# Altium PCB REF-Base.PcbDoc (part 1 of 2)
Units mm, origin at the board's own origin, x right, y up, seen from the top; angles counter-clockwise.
Board outline 48.01 x 58 mm, 4 copper layers (Top1, VCC, GND, Bottom2), stack 1.833 mm thick; 98 components, 129 nets, 444 pads, 192 vias.
Unrouted connection lines stored in the file: 57.
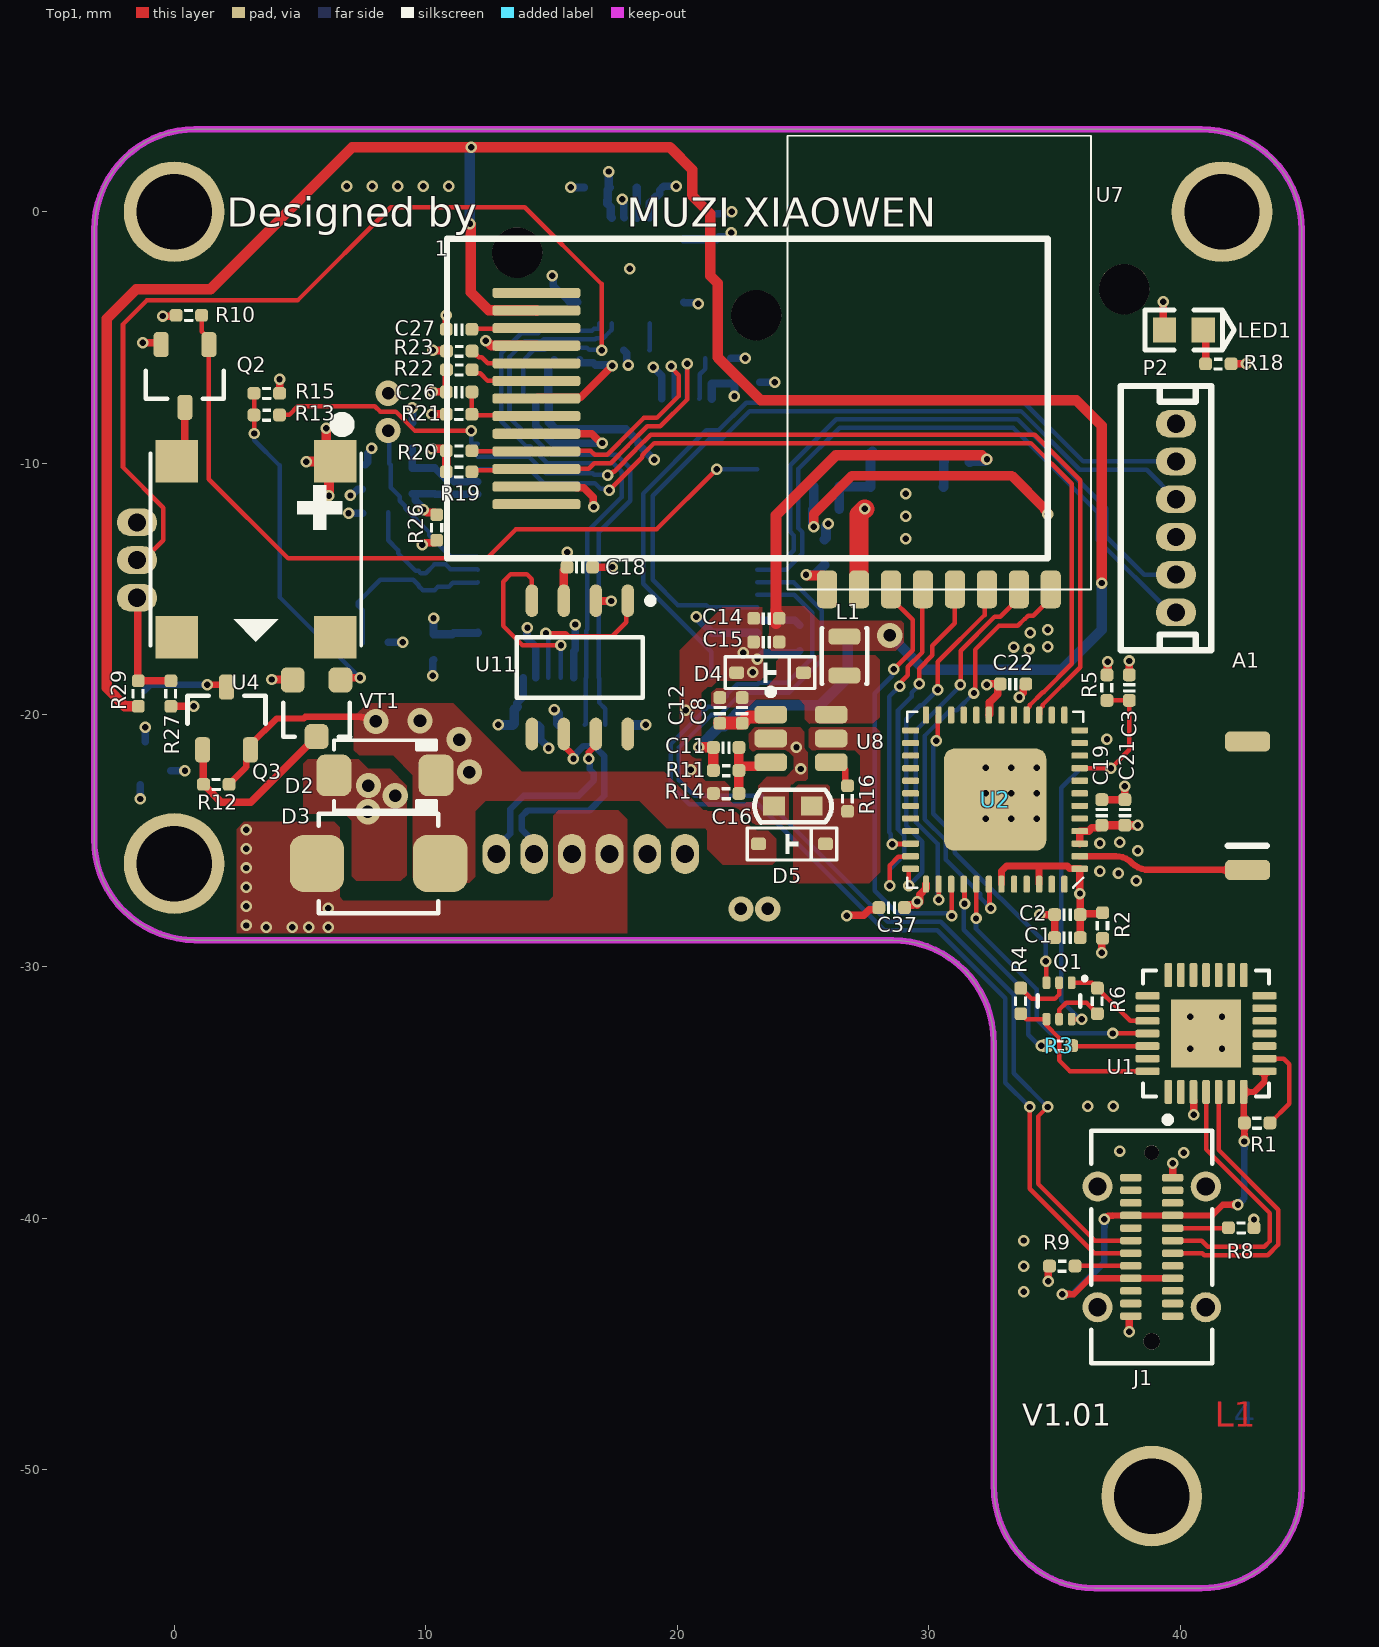
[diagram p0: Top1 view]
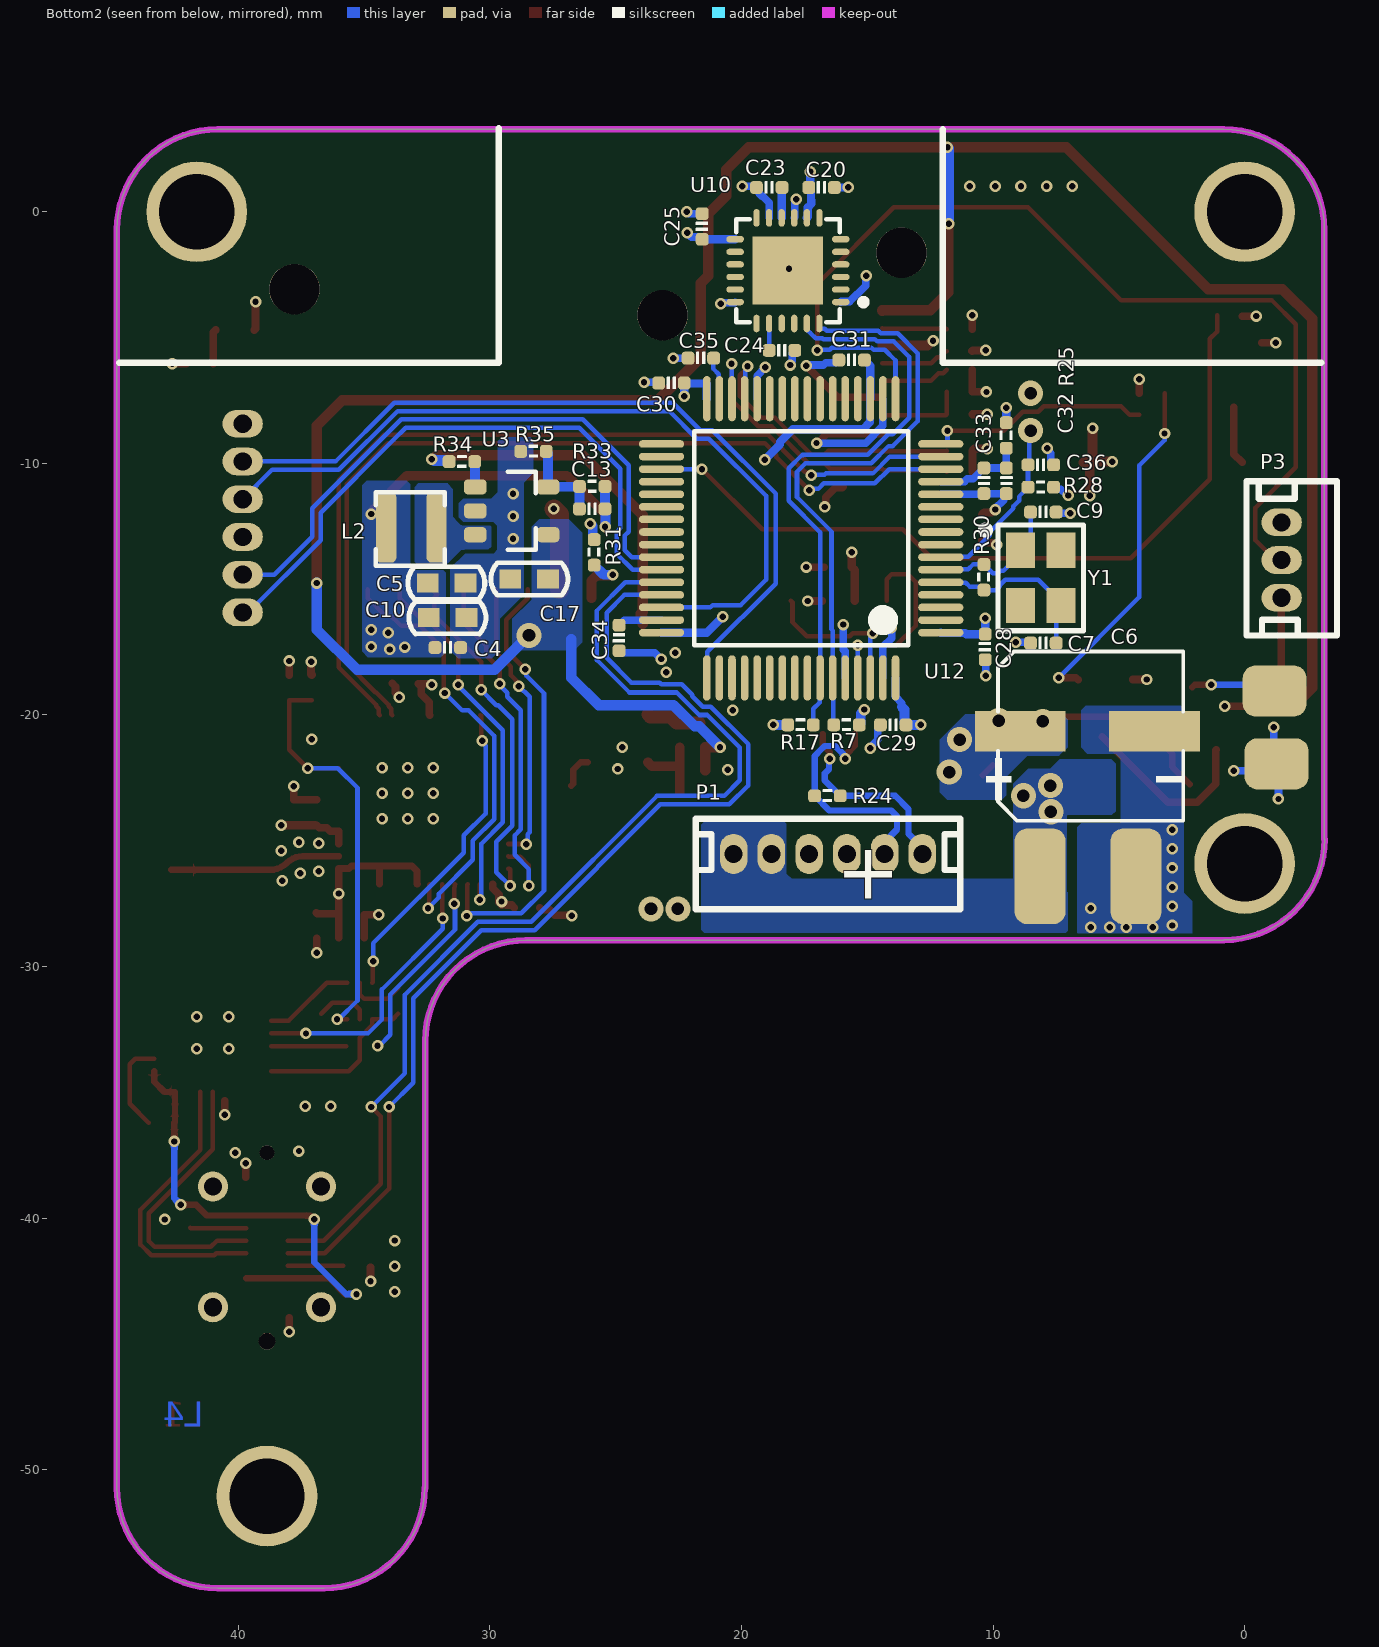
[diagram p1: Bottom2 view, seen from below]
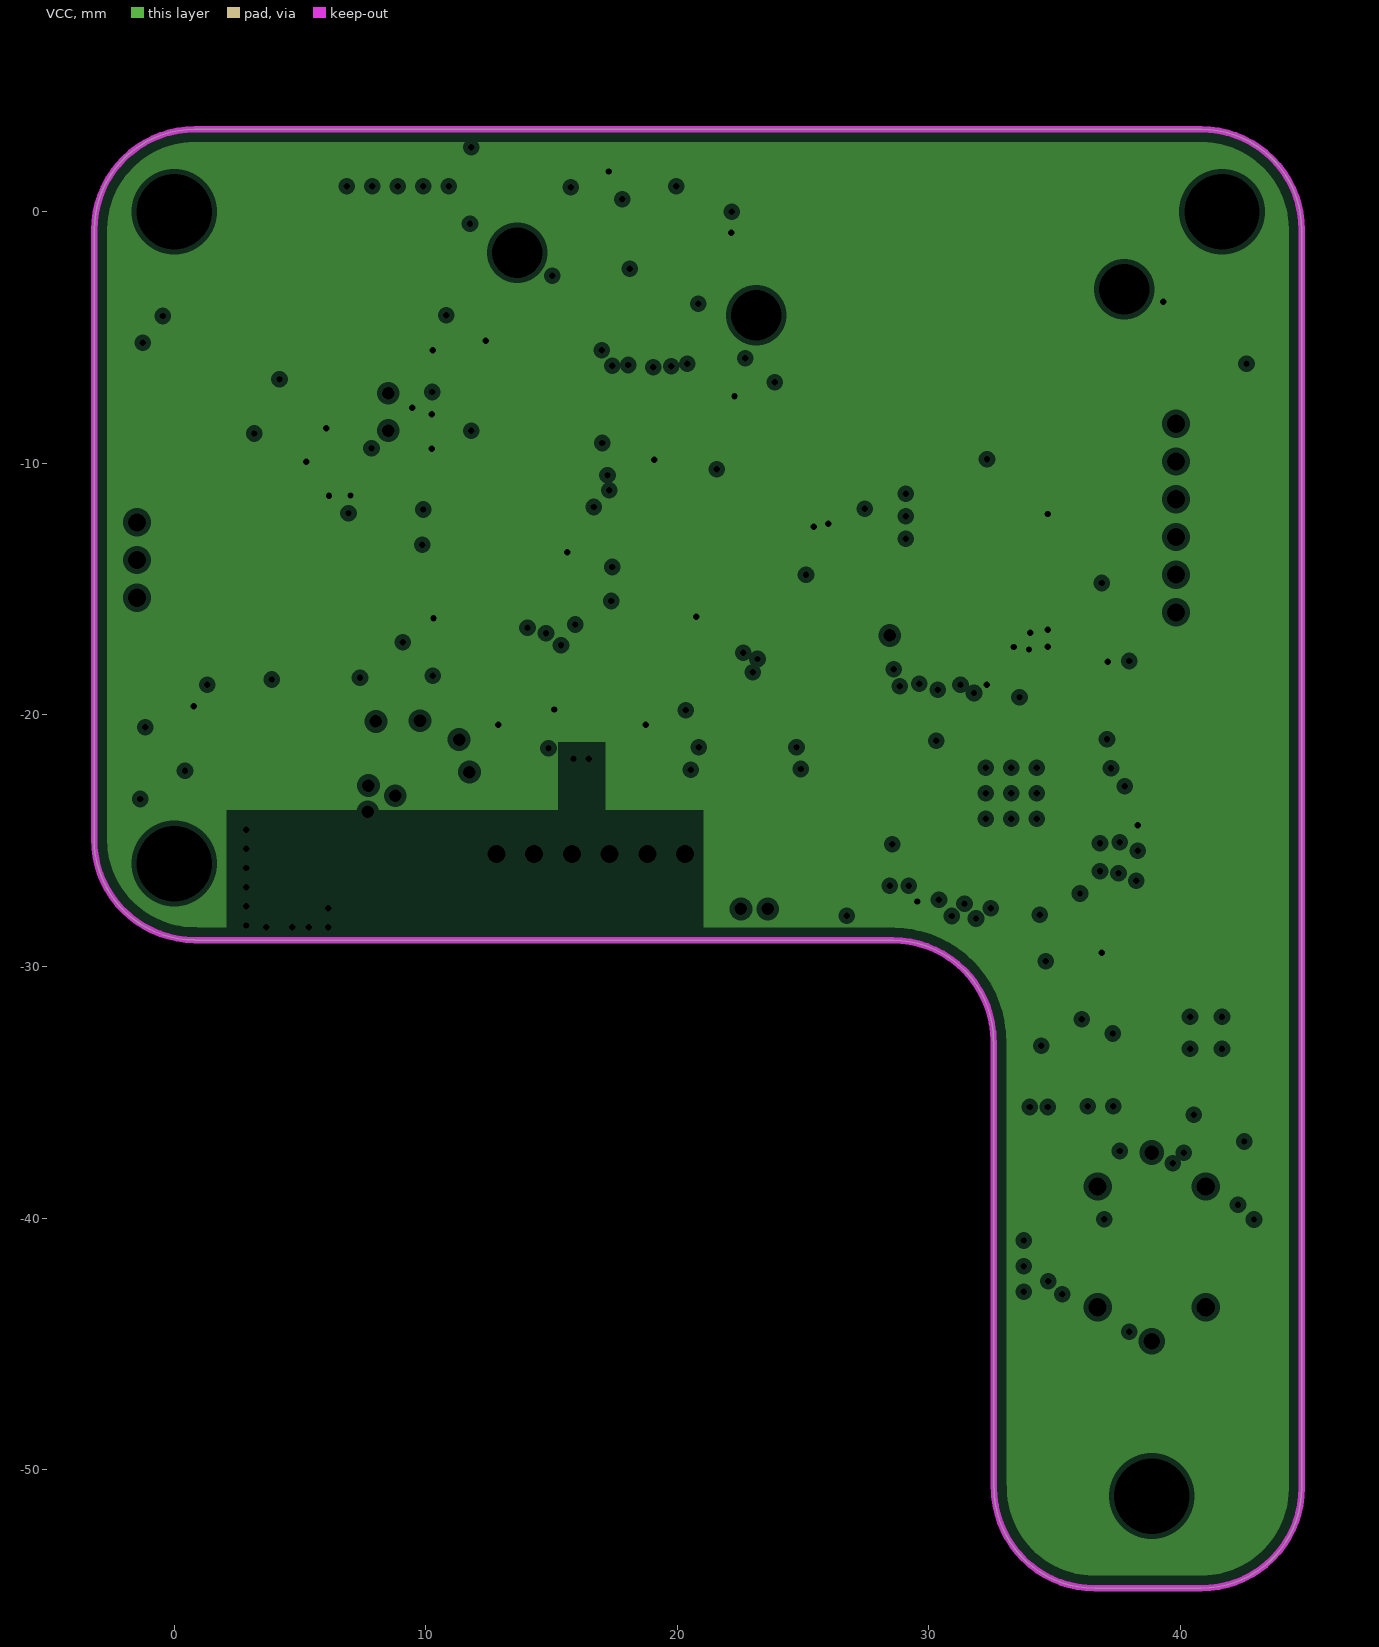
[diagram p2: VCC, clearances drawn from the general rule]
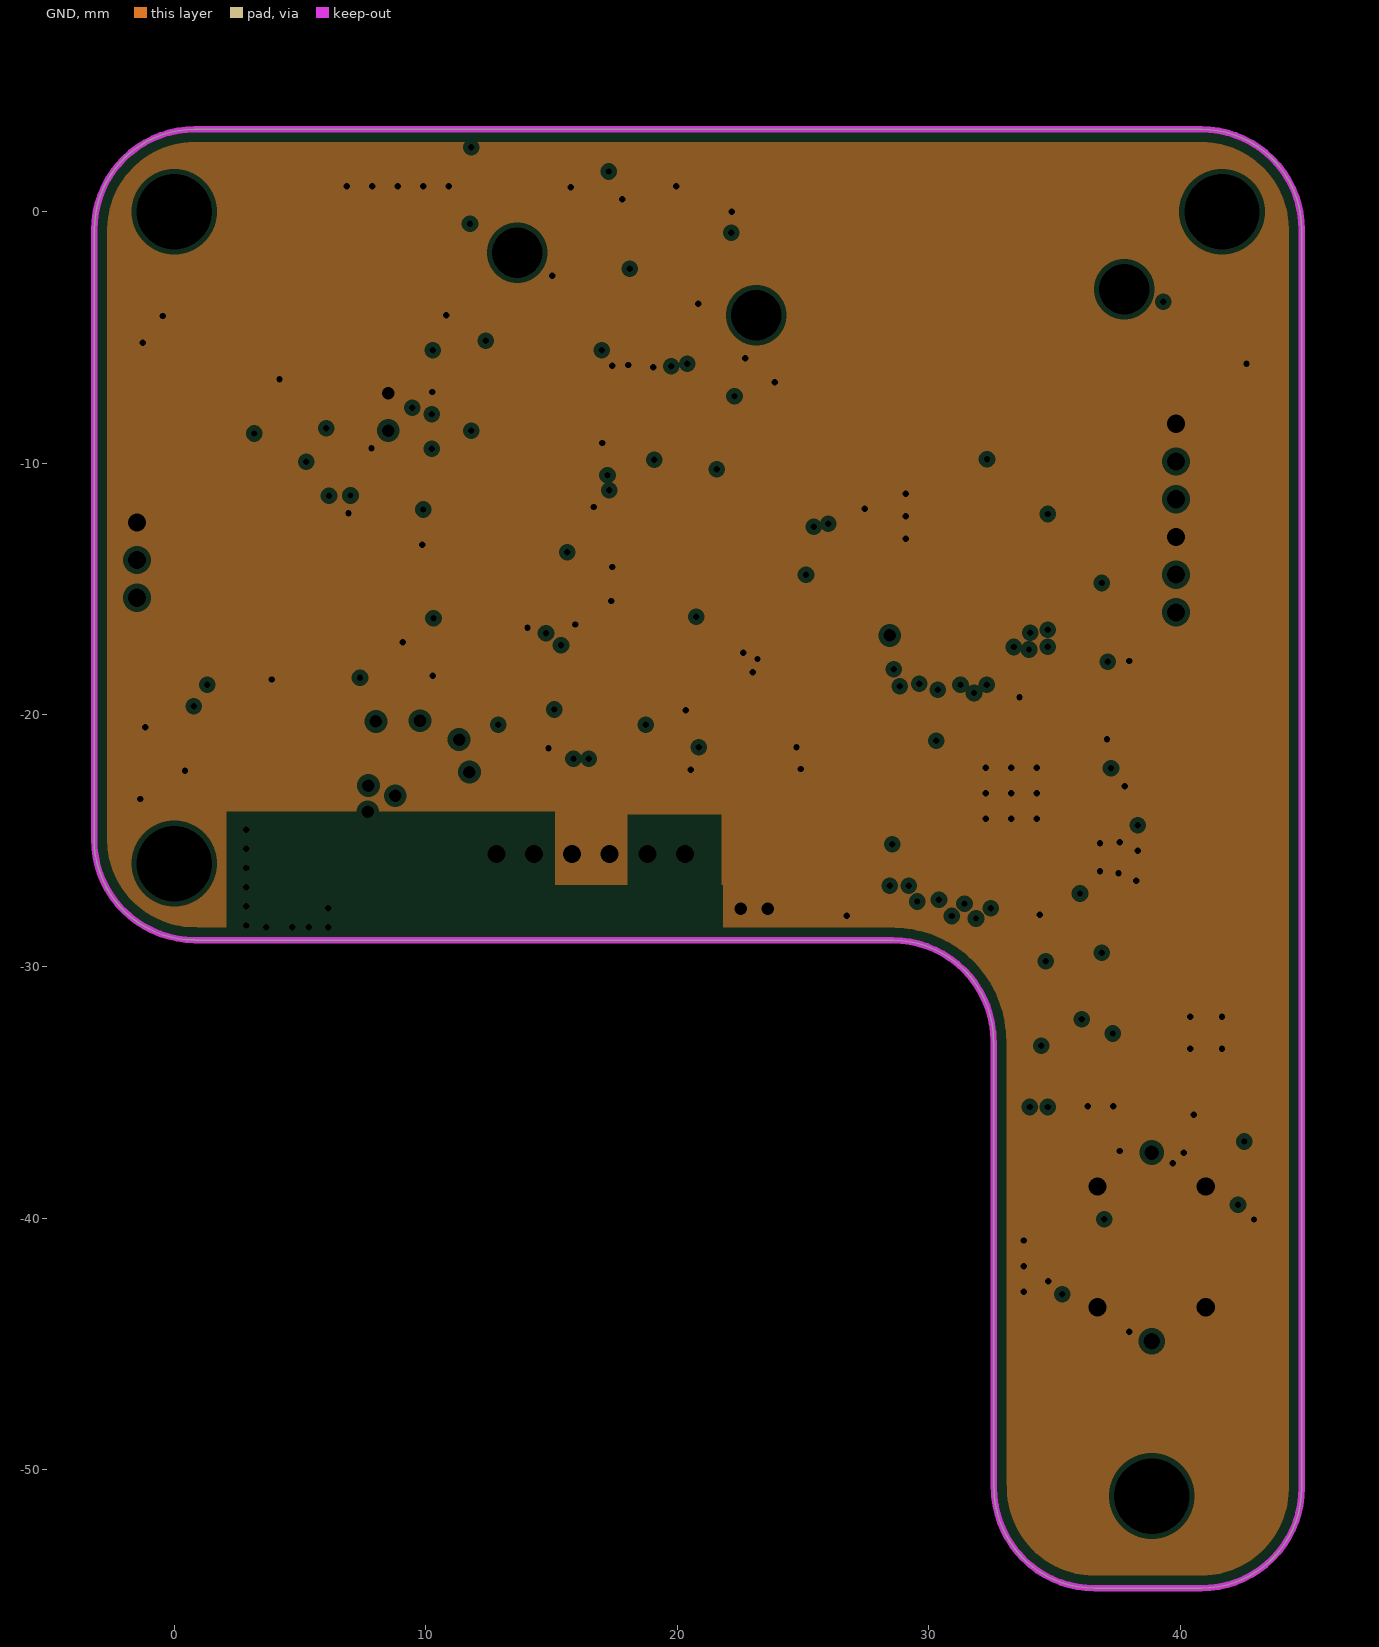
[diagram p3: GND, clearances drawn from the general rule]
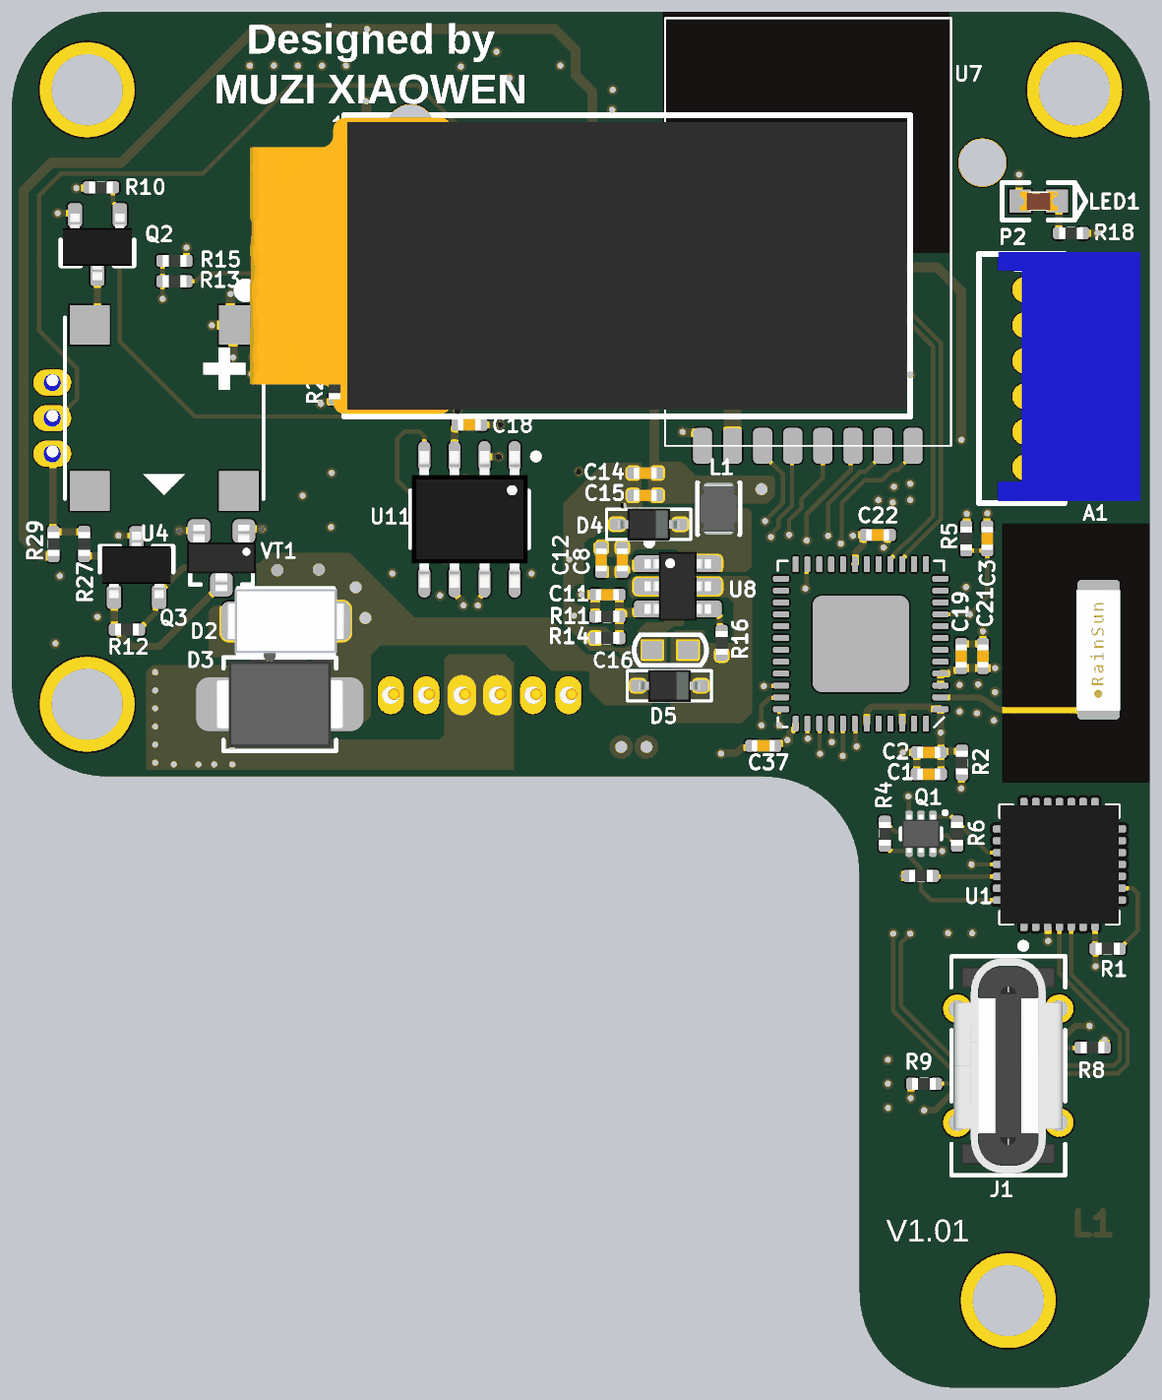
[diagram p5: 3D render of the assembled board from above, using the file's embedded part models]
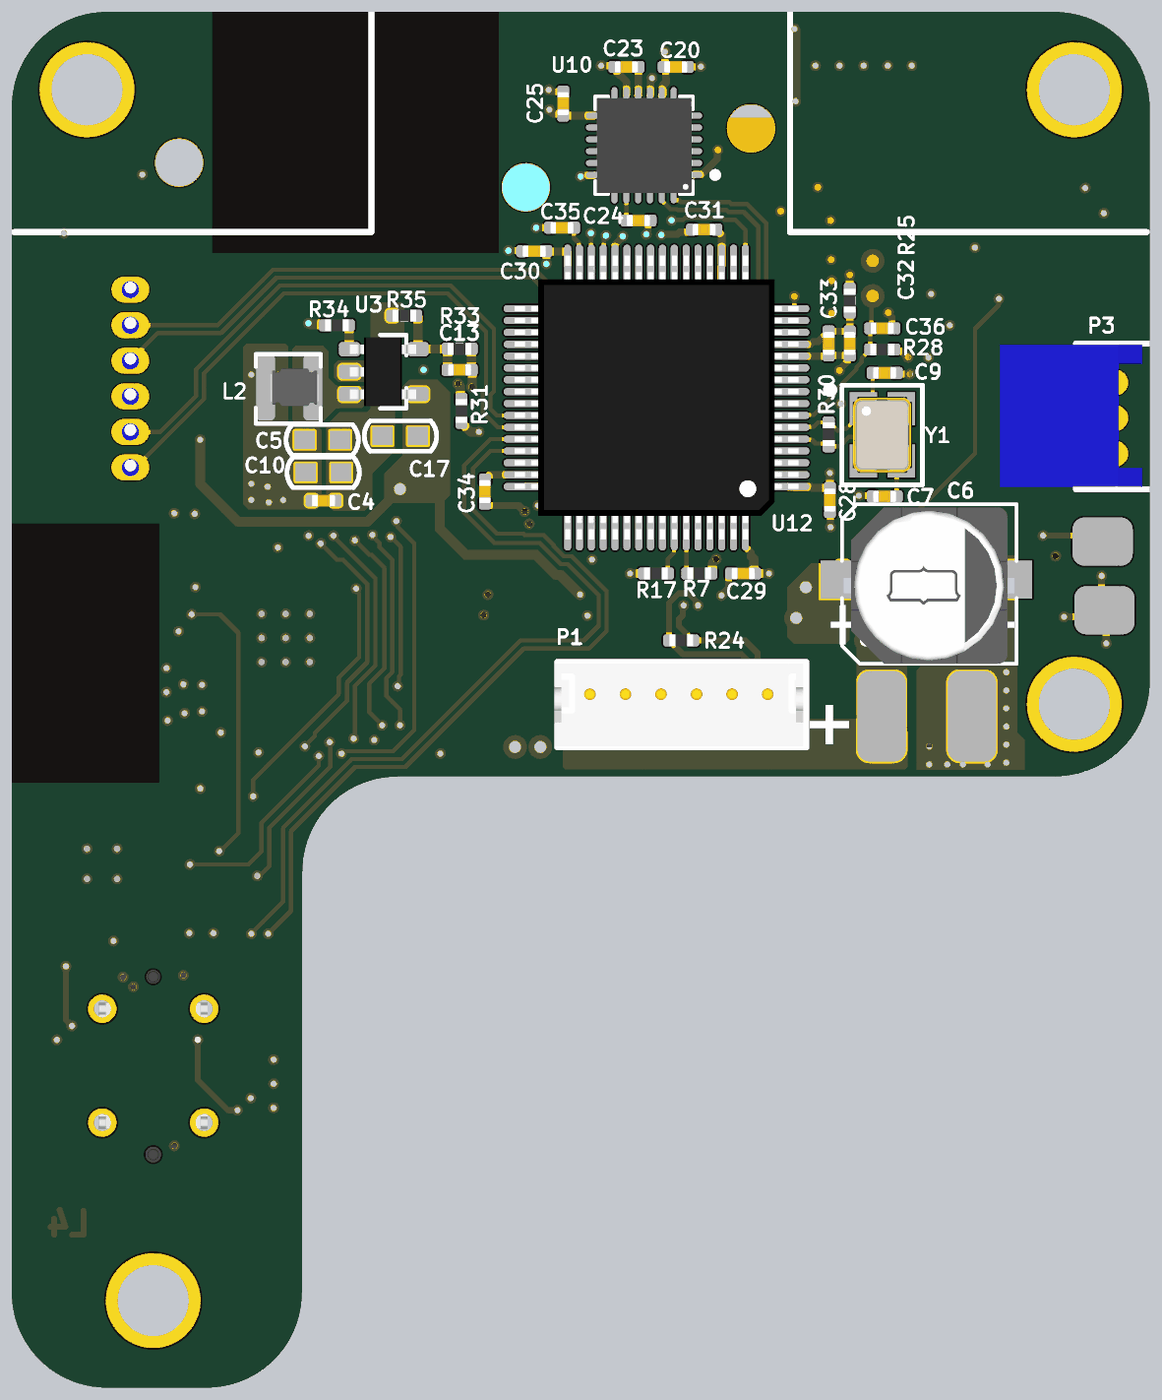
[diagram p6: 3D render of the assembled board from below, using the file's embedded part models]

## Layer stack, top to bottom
Top Solder: solder mask 0.0102, Solder Resist, Dk 3.5
Top1: signal copper 0.0356
Dielectric 1: prepreg 0.0711, PP-006, Dk 4.1
VCC: plane copper 0.035, net 3V3
Dielectric 2: prepreg 0.0711, PP-006, Dk 4.1
GND: plane copper 0.035, net GND
Dielectric1: core 1.55, FR-4, Dk 4.2
Bottom2: signal copper 0.0356
Bottom Solder: solder mask 0.0102, Solder Resist, Dk 3.5

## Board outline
-3.172,-24.948 -3.172,-0.719 cw(c0.828,-0.719) 0.828,3.281 40.828,3.281 cw(c40.828,-0.719) 44.828,-0.719 44.828,-50.719 cw(c40.828,-50.719) 40.828,-54.719 36.594,-54.719 cw(c36.594,-50.719) 32.594,-50.719 32.576,-50.737 32.576,-32.961 32.571,-32.961 ccw(c28.571,-32.961) 28.571,-28.961 28.571,-28.956 0.82,-28.956 0.82,-28.948 cw(c0.82,-24.948)

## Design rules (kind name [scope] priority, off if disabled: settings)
Clearance Clearance_Logo [InNetClass('Logo')] p1: gap=0.203 ignorepadtopadclearanceinfootprint=FALSE
Clearance [All] p2: gap=0.152 ignorepadtopadclearanceinfootprint=FALSE
ComponentClearance [All] p1: gap=0 collisioncheckmode=3 verticalgap=0 showdistances=FALSE
DiffPairsRouting [All] p1: maxlimit=0.229 minlimit=0.229 mostfreqgap=0.229 toplayer_minwidth=0.381 toplayer_maxwidth=0.381 toplayer_prefwidth=0.381 bottomlayer_minwidth=0.381 bottomlayer_maxwidth=0.381 bottomlayer_prefwidth=0.381 maxuncoupledlength=12.7
FanoutControl Fanout_BGA [All] p1: bgadir=Out bgaviamode=Centered fanoutstyle=Auto fanoutdirection=Alternating viagrid=0.025 // Fanout_BGA (Default Rule)
HoleSize [All] p1: absolutevalues=TRUE maxlimit=254 minlimit=0.203 maxpercent=80.000 minpercent=20.000
MinimumSolderMaskSliver [All] p1 off: minsoldermaskwidth=0.051
PlaneClearance [All] p1: clearance=0.203
PlaneConnect [All] p1: planeconnectstyle=Direct reliefexpansion=0.508 reliefentries=4 reliefconductorwidth=0.254 reliefairgap=0.254
PolygonConnect [All] p1: connectstyle=Direct reliefconductorwidth=0.254 reliefentries=4 polygonreliefangle="90 Angle" airgapwidth=0.254
RoomDefinition Main [InComponentClass('Main')] p1 off: confinementstyle=ConfineIn formatcopy=TRUE lockcomponents=FALSE outline -155.47,-131.137 -104.67,-131.137 -104.67,-105.737 -155.47,-105.737
RoutingVias [All] p1: holewidth=0.203 width=0.406 viastyle="Through Hole" minholewidth=0.152 minwidth=0.305 maxholewidth=0.711 maxwidth=1.27
SilkToSilkClearance [All] p1: silktosilkclearance=0
SilkToSolderMaskClearance [IsPad] p1: minsilkscreentomaskgap=0 clearancetoexposedcopper=TRUE
SolderMaskExpansion [All] p1: expansion=0.076 istentingtop=FALSE
Width Logo [InNetClass('Logo')] p1: maxlimit=2.54 minlimit=0.003 preferedwidth=0.254
Width GND [(InNet('AGND') OR InNet('GND'))] p2: maxlimit=1.27 minlimit=0.102 preferedwidth=0.254
Width VCC [(InNet('VDD_SYS_3.3V') OR InNet('VDD_AV_3.3V') OR InNet('VDD_5V') OR InNet('VDD1V2-SYS') OR InNet('VDD1V1-EPHY') OR InNet('VDD-CPUX') OR InNet('VDD-CPUS') OR InNet('VDD-CPUFB') OR InNet('VCC-DRAM'))] p3: maxlimit=1.27 minlimit=0.102 preferedwidth=0.254
Width [All] p4: maxlimit=254 minlimit=0.102 preferedwidth=0.102
21 further rules are at their usual default settings.

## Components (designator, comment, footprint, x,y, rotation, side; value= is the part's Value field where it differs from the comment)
1 "OLED-12880" OLED-12880 14.402,-7.425 r180 top locked
A1 "RAINSUN" ANT-Rainsun-AN5120 42.672,-23.622 r90 top
C1 "10uF" CAP_0402 35.509,-28.854 r0 top value=0.1u
C2 "0.1uF" CAP_0402 35.509,-27.94 r0 top value=0.1u
C3 "1uF" CAP_0402 37.973,-18.917 r90 top value=0.1u
C4 "0.1uF" CAP_0402 31.674,-17.323 r0 bottom value=0.1u
C5 "22uF" C0603 31.741,-14.754 r0 bottom
C6 "220uF/25V" CAP-SMD_BD8.0-L8.3-W8.3-LS9.3-FD 6.375,-20.65 r180 bottom value=150uF/35V
C7 "20pF" CAP_0402 8.001,-17.145 r0 bottom
C8 "0.1uF" CAP_0402 22.581,-19.82 r270 top value=0.1u
C9 "20pF" CAP_0402 8.001,-11.938 r180 bottom
C10 "22uF" C0603 31.699,-16.129 r0 bottom
C11 "100pF" CAP_0402 21.946,-21.293 r0 top value=0.1u
C12 "0.1uF" CAP_0402 21.692,-19.82 r270 top value=0.1u
C13 "22pF" CAP_0402 25.933,-11.811 r180 bottom
C14 "0.1uF" CAP_0402 23.546,-16.162 r0 top value=0.1u
C15 "10uF" CAP_0402 23.546,-17.102 r0 top value=0.1u
C16 "4.7uF" C0603 24.613,-23.63 r0 top value="4.7uF 35V"
C17 "22uF" C0603 28.423,-14.605 r180 bottom
C18 "0.1uF" CAP_0402 16.129,-14.122 r180 top value=0.1u
C19 "0.1uF" CAP_0402 36.881,-23.876 r270 top value=0.1u
C20 "10nF" CAP_0402 16.815,0.965 r180 bottom value=0.1u
C21 "0.1uF" CAP_0402 37.795,-23.876 r270 top value=0.1u
C22 "0.1uF" CAP_0402 33.35,-18.771 r180 top value=0.1u
C23 "0.1uF" CAP_0402 18.898,0.965 r0 bottom value=0.1u
C24 "2.2nF" CAP_0402 18.39,-5.512 r0 bottom value=0.1u
C25 "0.1uF" CAP_0402 21.565,-0.584 r270 bottom value=0.1u
C26 "10uF" CAP_0402 11.328,-7.163 r0 top value=0.1u
C27 "10uF" CAP_0402 11.328,-4.674 r0 top value=0.1u
C28 "0.1uF" CAP_0402 10.312,-17.297 r90 bottom value=0.1u
C29 "0.1uF" CAP_0402 13.97,-20.396 r180 bottom value=0.1u
C30 "0.1uF" CAP_0402 22.784,-6.807 r180 bottom value=0.1u
C31 "0.1uF" CAP_0402 15.621,-5.893 r180 bottom value=0.1u
C32 "0.1uF" CAP_0402 9.474,-10.693 r90 bottom value=0.1u
C33 "10uF" CAP_0402 10.363,-10.693 r90 bottom value=0.1u
C34 "10uF" CAP_0402 24.867,-16.942 r90 bottom value=0.1u
C35 "10uF" CAP_0402 21.615,-5.817 r180 bottom value=0.1u
C36 "0.1uF" CAP_0402 8.103,-10.058 r0 bottom value=0.1u
C37 "0.1uF" CAP_0402 28.524,-27.661 r0 top value=0.1u
D2 "SS54" DO-214AC 8.382,-22.403 r0 top
D3 "SMBJ28CA" SMBJ-CA_MFG 8.128,-25.908 r0 top
D4 "二极管-5819W" SOD-323 23.69,-18.321 r0 top
D5 "二极管-5819W" SOD-323 24.562,-25.129 r0 top
J1 "USB-TYPE-C-STAND" USB-TYPE-C-STAND 38.862,-41.148 r90 top
L1 "6.8uH" IND-201612 26.645,-17.661 r90 top
L2 "2.2uH" IND-252012A-2R2 33.122,-12.548 r0 bottom
LED1 "LED GREEN" LED-0603 40.138,-4.699 r180 top
P1 "Header 6H" CONN-TH_HC-ZH1.5-6A 16.561,-25.527 r180 bottom
P2 "Header 6H" CONN-TH_HC-ZH1.5-6A-s 39.827,-12.176 r270 top
P3 "Header 3" CONN-TH_HC-ZH1.5-3A-S -1.473,-13.844 r90 bottom locked
Q1 "BC847BVC-7" SOT563-6 35.179,-31.369 r180 top
Q2 "AO3400A" SOT23-3 0.432,-6.528 r270 top
Q3 "AO3401A" SOT23-3 2.083,-20.142 r90 top
R1 "10K" RES_0402_1 43.053,-36.22 r0 top value=22R
R2 "0R" RES_0402_1 36.906,-28.372 r90 top value=22R
R3 "200R" RES_0402_1 35.179,-33.147 r0 top value=22R
R4 "12K" RES_0402_1 33.655,-31.369 r90 top value=22R
R5 "10K" RES_0402_1 37.084,-18.917 r270 top value=22R
R6 "12K" RES_0402_1 36.703,-31.369 r270 top value=22R
R7 "2K" RES_0402_1 15.824,-20.396 r180 bottom value=22R
R8 "5.1K" RES_0402_1 42.418,-40.386 r0 top value=22R
R9 "5.1K" RES_0402_1 35.306,-41.91 r180 top value=22R
R10 "10K" RES_0402_1 0.584,-4.115 r0 top value=22R
R11 "10K" RES_0402_1 21.946,-22.208 r180 top value=22R
R12 "2K" RES_0402_1 1.676,-22.758 r0 top value=22R
R13 "1K" RES_0402_1 3.683,-8.077 r180 top value=22R
R14 "1.8K" RES_0402_1 21.946,-23.122 r0 top value=22R
R15 "10K" RES_0402_1 3.683,-7.214 r0 top value=22R
R16 "1M" RES_0402_1 26.772,-23.325 r90 top value=22R
R17 "2K" RES_0402_1 17.653,-20.396 r0 bottom value=22R
R18 "2K" RES_0402_1 41.51,-6.045 r180 top value=22R
R19 "4.7K" RES_0402_1 11.328,-10.338 r180 top value=22R
R20 "4.7K" RES_0402_1 11.328,-9.5 r180 top value=22R
R21 "10K" RES_0402_1 11.328,-8.052 r180 top value=22R
R22 "560K" RES_0402_1 11.335,-6.279 r180 top value=22R
R23 "4.7K" RES_0402_1 11.335,-5.537 r180 top value=22R
R24 "120R/NC" RES_0402_1 16.586,-23.216 r0 bottom value=22R
R25 "0R" RES_0402_1 9.474,-8.89 r90 bottom value=22R
R26 "0R" RES_0402_1 10.439,-12.548 r270 top value=22R
R27 "0R" RES_0402_1 -0.127,-19.152 r270 top
R28 "10K" RES_0402_1 8.103,-10.947 r180 bottom value=22R
R29 "0R" RES_0402_1 -1.422,-19.152 r270 top
R30 "1M" RES_0402 10.363,-14.529 r90 bottom value=22R
R31 "0R" RES_0402_1 25.857,-13.538 r270 bottom
R33 "100K" RES_0402_1 25.933,-10.922 r180 bottom
R34 "10K" RES_0402_1 31.115,-9.931 r0 bottom value=22R
R35 "22.1K" RES_0402_1 28.27,-9.525 r180 bottom
U1 "CP2102" QFN-28 41.021,-32.664 r90 top value=Value
U2 "ESP32_SIP" QFN-48_7X7 32.639,-23.368 r180 top locked
U3 "SY8089 2A" SOT23-5 29.083,-11.887 r0 bottom
U4 "MLT-7525" BUZ-SMD_4P-L7.5-W7.5-P7.59-TL 3.251,-13.411 r270 top
U7 "NRF24L01" NRF24L01-MODULE 25.959,-15.011 r0 top locked
U8 "ME3116" SOT23-6 24.917,-20.938 r0 top
U10 "MPU6050" QFN-24 18.153,-2.341 r180 bottom
U11 "SN65HVD232D" SO-8 16.129,-18.11 r90 top
U12 "STM32F405RGT6" LQFP-64_N 17.628,-12.979 r180 bottom locked
VT1 "S8050" SMT_TRIODE_NPN 5.664,-19.736 r180 top
Y1 "XTAL-4" LC-SMD-3225_4P 8.103,-14.554 r270 bottom value=8MHz

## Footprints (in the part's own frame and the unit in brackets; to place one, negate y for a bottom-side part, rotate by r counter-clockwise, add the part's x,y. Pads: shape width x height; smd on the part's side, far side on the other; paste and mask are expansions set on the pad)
ANT-Rainsun-AN5120 [mm] "Ñ¡Ôñº¸ÅÌ"
  rrect50% 0.8x1.8 smd: 1(-2.54,0) ""(2.563,0)
  silkscreen extent -1.57,-0.76 -1.57,0.79, body extent -2.57,-0.91 2.54,0.94, height 1.32
BUZ-SMD_4P-L7.5-W7.5-P7.59-TL [mm]
  rect 1.681x1.68 smd: 1(-3.497,3.15) 2(-3.497,-3.15) 3(3.497,-3.15) 4(3.497,3.15)
  silkscreen extent -5.2,-4.19 3.84,4.19, body extent -4.45,-4.06 4.45,4.06, height 2.5
C0603 [mm]
  rect 0.86x0.76 smd: 1(-0.768,0.005) 2(0.732,0.005)
  silkscreen extent -1.53,-0.64 1.52,0.65, body extent -1.5,-0.75 1.5,0.75, height 1.5
CAP-SMD_BD8.0-L8.3-W8.3-LS9.3-FD [mm]
  rect 3.6x1.6 smd: 1(-2.54,0) 2(2.794,0)
  silkscreen extent -3.9,-3.56 3.94,3.18, body extent -3.35,-3.55 3.85,3.05, height 7.7
CAP_0402 [mil]
  rrect50% 20x20 smd: 1(-20,0) 2(20,0)
  silkscreen extent -6,-9 6,9, body extent -20,-10 20,10, height 20
CONN-TH_HC-ZH1.5-3A-S [mm]
  oval 1.1x1.6 hole 0.72 paste+0 mask+0.05: 1(-1.5,0) 2(0,0) 3(1.5,0)
  silkscreen extent -3,-2.2 3.14,1.4, body extent -2.9,-1.39 3.1,4.61, height 4
CONN-TH_HC-ZH1.5-6A [mm]
  oval 1.1x1.6 hole 0.72 paste+0 mask+0.05: 1(-3.75,0) 2(-2.25,0) 3(-0.75,0) 4(0.75,0) 5(2.25,0) 6(3.75,0)
  silkscreen extent -5.25,-2.2 5.25,1.4, body extent -5.38,-2.16 5.12,1.34, height 4.04
CONN-TH_HC-ZH1.5-6A-s [mm]
  oval 1.1x1.6 hole 0.72 paste+0 mask+0.05: 1(-3.75,0) 2(-2.25,0) 3(-0.75,0) 4(0.75,0) 5(2.25,0) 6(3.75,0)
  silkscreen extent -5.25,-2.2 5.25,1.4, body extent -5.34,-1.4 5.16,4.6, height 4
DO-214AC [mil] "SMA"
  rrect50% 55x65 smd: 1(-80,0) 2(80,0)
  silkscreen extent -80,-55 80,55, body extent -98,-53 98,53, height 85
IND-201612 [mm]
  rrect50% 0.635x1.27 smd paste+0 mask+0: 1(-0.774,0) 2(0.774,0)
  silkscreen extent -1.1,-0.9 1.1,0.9, body extent -1,-0.8 1,0.8, height 0.95
IND-252012A-2R2 [mm]
  rrect50% 0.8x2.8 smd paste+0 mask+0: 1(-1,0) 2(1,0)
  silkscreen extent -1.33,-1.4 1.41,1.52, body extent -1.23,-0.8 0.77,0.8, height 0.95
LC-SMD-3225_4P [mm]
  rect 1.4x1.15 smd: 1(-1.1,-0.8) 2(1.1,-0.8) 3(1.1,0.8) 4(-1.1,0.8)
  silkscreen extent -2.1,-2.35 2.1,1.7, body extent -1.6,-1.25 1.6,1.25, height 0.61
LED-0603 [mm]
  rect 0.93x0.98 smd: A(0.77,0) C(-0.77,0)
  silkscreen extent -2,-0.79 1.54,0.79, body extent -0.8,-0.4 0.8,0.4, height 0.6
LQFP-64_N [mm] "Thin QFP, 64-Leads, Body 10x10mm, Pitch 0.5mm, IPC Medium Density"
  oval 1.8x0.3 smd: 1(5.55,-3.75) 2(5.55,-3.25) 3(5.55,-2.75) 4(5.55,-2.25) 5(5.55,-1.75) 6(5.55,-1.25) 7(5.55,-0.75) 8(5.55,-0.25) 9(5.55,0.25) 10(5.55,0.75) 11(5.55,1.25) 12(5.55,1.75) 13(5.55,2.25) 14(5.55,2.75) 15(5.55,3.25) 16(5.55,3.75) 33(-5.55,3.75) 34(-5.55,3.25) 35(-5.55,2.75) 36(-5.55,2.25) 37(-5.55,1.75) 38(-5.55,1.25) 39(-5.55,0.75) 40(-5.55,0.25) 41(-5.55,-0.25) 42(-5.55,-0.75) 43(-5.55,-1.25) 44(-5.55,-1.75) 45(-5.55,-2.25) 46(-5.55,-2.75) 47(-5.55,-3.25) 48(-5.55,-3.75)
  oval 0.3x1.8 smd: 17(3.75,5.55) 18(3.25,5.55) 19(2.75,5.55) 20(2.25,5.55) 21(1.75,5.55) 22(1.25,5.55) 23(0.75,5.55) 24(0.25,5.55) 25(-0.25,5.55) 26(-0.75,5.55) 27(-1.25,5.55) 28(-1.75,5.55) 29(-2.25,5.55) 30(-2.75,5.55) 31(-3.25,5.55) 32(-3.75,5.55) 49(-3.75,-5.55) 50(-3.25,-5.55) 51(-2.75,-5.55) 52(-2.25,-5.55) 53(-1.75,-5.55) 54(-1.25,-5.55) 55(-0.75,-5.55) 56(-0.25,-5.55) 57(0.25,-5.55) 58(0.75,-5.55) 59(1.25,-5.55) 60(1.75,-5.55) 61(2.25,-5.55) 62(2.75,-5.55) 63(3.25,-5.55) 64(3.75,-5.55)
  silkscreen extent -4.25,-4.25 4.25,4.25, body extent -5.98,-5.98 5.99,5.99, height 1.6
NRF24L01-MODULE [mm]
  rrect50% 0.8x1.5 smd: 1(0,0) 2(1.27,0) 3(2.54,0) 4(3.81,0) 5(5.08,0) 6(6.35,0) 7(7.62,0) 8(8.89,0)
  silkscreen extent -1.57,0 10.49,18.03
OLED-12880 [mm]
  rrect50% 3.5x0.4 smd: 1(0,-4.2) 2(0,-3.5) 3(0,-2.8) 4(0,-2.1) 5(0,-1.4) 6(0,-0.7) 7(0,0) 8(0,0.7) 9(0,1.4) 10(0,2.1) 11(0,2.8) 12(0,3.5) 13(0,4.2)
  silkscreen extent -20.32,-6.35 3.56,6.35, body extent -20.18,-6.25 7.54,6.25, height 1.55
QFN-24 [mm] "QFN, 24-Leads, Body 4.1x4.1mm (max), Pitch 0.50mm, IPC Low Density"
  oval 0.7x0.25 smd: 1(2.1,-1.25) 2(2.1,-0.75) 3(2.1,-0.25) 4(2.1,0.25) 5(2.1,0.75) 6(2.1,1.25) 13(-2.1,1.25) 14(-2.1,0.75) 15(-2.1,0.25) 16(-2.1,-0.25) 17(-2.1,-0.75) 18(-2.1,-1.25)
  oval 0.25x0.7 smd: 7(1.25,2.1) 8(0.75,2.1) 9(0.25,2.1) 10(-0.25,2.1) 11(-0.75,2.1) 12(-1.25,2.1) 19(-1.25,-2.1) 20(-0.75,-2.1) 21(-0.25,-2.1) 22(0.25,-2.1) 23(0.75,-2.1) 24(1.25,-2.1)
  rect 2.8x2.7 smd: ""(0,0)
  silkscreen extent -2.05,-2.05 3.12,2.05, body extent -2.02,-2.02 2.02,2.02, height 0.95
QFN-28 [mil]
  rrect50% 38x12 smd mask+5: 1(-91.5,59.06) 2(-91.5,39.37) 3(-91.5,19.68) 4(-91.5,0) 5(-91.5,-19.69) 6(-91.5,-39.37) 7(-91.5,-59.06) 15(91.5,-59.06) 16(91.5,-39.37) 17(91.5,-19.69) 18(91.5,0) 19(91.5,19.68) 20(91.5,39.37) 21(91.5,59.06)
  rrect50% 12x38 smd mask+5: 8(-59.06,-91.5) 9(-39.37,-91.5) 10(-19.68,-91.5) 11(0,-91.5) 12(19.68,-91.5) 13(39.37,-91.5) 14(59.06,-91.5) 22(59.06,91.5) 23(39.37,91.5) 24(19.68,91.5) 25(0,91.5) 26(-19.68,91.5) 27(-39.37,91.5) 28(-59.06,91.5)
  rect 106.3x110.24 smd: 29(0,0)
  silkscreen extent -140,-98 98,98, body extent -98,-98 98,98, height 35
QFN-48_7X7 [mm]
  rrect50% 0.675x0.25 smd: 1(-3.363,2.75) 2(-3.363,2.25) 3(-3.363,1.75) 4(-3.363,1.25) 5(-3.363,0.75) 6(-3.363,0.25) 7(-3.363,-0.25) 8(-3.363,-0.75) 9(-3.363,-1.25) 10(-3.363,-1.75) 11(-3.363,-2.25) 12(-3.363,-2.75) 25(3.363,-2.75) 26(3.363,-2.25) 27(3.363,-1.75) 28(3.363,-1.25) 29(3.363,-0.75) 30(3.363,-0.25) 31(3.363,0.25) 32(3.363,0.75) 33(3.363,1.25) 34(3.363,1.75) 35(3.363,2.25) 36(3.363,2.75)
  rrect50% 0.25x0.675 smd: 13(-2.75,-3.363) 14(-2.25,-3.363) 15(-1.75,-3.363) 16(-1.25,-3.363) 17(-0.75,-3.363) 18(-0.25,-3.363) 19(0.25,-3.363) 20(0.75,-3.363) 21(1.25,-3.363) 22(1.75,-3.363) 23(2.25,-3.363) 24(2.75,-3.363) 37(2.75,3.363) 38(2.25,3.363) 39(1.75,3.363) 40(1.25,3.363) 41(0.75,3.363) 42(0.25,3.363) 43(-0.25,3.363) 44(-0.75,3.363) 45(-1.25,3.363) 46(-1.75,3.363) 47(-2.25,3.363) 48(-2.75,3.363)
  rrect20% 4.064x4.064 smd: 49(0,0)
  silkscreen extent -3.5,-3.5 3.5,3.5, body extent -3.5,-3.5 3.5,3.5, height 1
RES_0402 [mil]
  rrect50% 20x20 smd: 1(-20,0) 2(20,0)
  silkscreen extent -7,-10 7,10, body extent -20,-10 20,10, height 14
RES_0402_1 [mil]
  rrect50% 20x20 smd: 1(-20,0) 2(20,0)
  silkscreen extent -6,-10 6,10, body extent -20,-10 20,10, height 14
SMBJ-CA_MFG [mm]
  rrect50% 2.16x2.26 smd paste+0 mask+0: 1(-2.45,0) 2(2.45,0)
  silkscreen extent -2.37,-1.97 2.37,1.97, body extent -2.7,-1.81 2.7,1.81, height 2.62
SMT_TRIODE_NPN [mm] "Surface mount NPN transistor, package SOT-23"
  rrect50% 0.95x1 smd: 1(-0.95,-1.125) 2(0.95,-1.125) 3(0,1.125)
  silkscreen extent -1.33,-0.22 1.32,1.13, body extent -1.45,-1.4 1.45,1.4, height 1.3
SO-8 [mm]
  oval 1.3x0.5 smd: 1(2.65,-1.905) 2(2.65,-0.635) 3(2.65,0.635) 4(2.65,1.905) 5(-2.65,1.905) 6(-2.65,0.635) 7(-2.65,-0.635) 8(-2.65,-1.905)
  silkscreen extent -1.2,-2.93 2.77,2.5, body extent -2.89,-2.46 2.89,2.44, height 1.45
SOD-323 [mm]
  rrect50% 0.6x0.5 smd: 1(-1.329,0) 2(1.329,0)
  silkscreen extent -1.78,-0.64 1.78,0.64, body extent -1.3,-0.68 1.3,0.67, height 1.15
SOT23-3 [mm] "SOT23, 3-Leads, Body 3.1x3.0mm (max), Pitch 0.95mm, IPC Medium Density"
  rrect50% 1x0.6 smd: 1(-1.246,0.95) 2(-1.246,-0.95) 3(1.246,0)
  silkscreen extent -0.2,-1.55 0.9,1.55, body extent -1.3,-1.45 1.5,1.45, height 1.2
SOT23-5 [mm] "SOT23, 3-Leads, Body 3.1x3.0mm (max), Pitch 0.95mm, IPC Medium Density"
  rrect50% 0.889x0.6 smd: 1(1.5,-0.95) 2(1.5,0) 3(1.5,0.95) 4(-1.396,0.95) 5(-1.396,-0.95)
  silkscreen extent -0.9,-1.55 0.2,1.55, body extent -1.32,-1.45 1.48,1.45, height 1.2
SOT23-6 [mm]
  rrect50% 1.3x0.7 smd: 1(-1.2,0.95) 2(-1.2,0) 3(-1.2,-0.95) 4(1.2,-0.95) 5(1.2,0) 6(1.2,0.95)
  silkscreen extent -1.32,1.73 -1.07,1.97, body extent -1.4,-1.45 1.4,1.45, height 1.45
SOT563-6 [mm]
  rrect50% 0.305x0.5 smd paste+0 mask+0: 1(-0.5,-0.723) 2(0,-0.723) 3(0.5,-0.723) 4(0.5,0.723) 5(0,0.723) 6(-0.5,0.723)
  silkscreen extent -1.09,-0.97 0.85,0.23, body extent -0.8,-0.8 0.8,0.8, height 0.6
USB-TYPE-C-STAND [mm]
  rrect50% 0.3x0.85 smd: A1(-2.75,0.83) A2(-2.25,0.83) A3(-1.75,0.83) A4(-1.25,0.83) A5(-0.75,0.83) A6(-0.25,0.83) A7(0.25,0.83) A8(0.75,0.83) A9(1.25,0.83) A10(1.75,0.83) A11(2.25,0.83) A12(2.75,0.83) B1(2.75,-0.83) B2(2.25,-0.83) B3(1.75,-0.83) B4(1.25,-0.83) B5(0.75,-0.83) B6(0.25,-0.83) B7(-0.25,-0.83) B8(-0.75,-0.83) B9(-1.25,-0.83) B10(-1.75,-0.83) B11(-2.25,-0.83) B12(-2.75,-0.83)
  round 1.2 hole 0.72: S1(-2.4,2.15) S2(2.4,2.15) S3(-2.4,-2.15) S4(2.4,-2.15)
  round 0.66 hole 0.66 unplated: ""(-3.75,0)
  round 0.58 hole 0.58 unplated: ""(3.75,0)
  silkscreen extent -4.62,-2.4 4.62,2.4, body extent -4.52,-2.3 4.52,2.3, height 7.39

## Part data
A1: library part ANT-Rainsun-AP5120
C1 C2 C3 C4 C5 C7 C8 C9 C10 C11 C12 C13 C14 C15 C16 C17 C18 C19 C20 C21 C22 C23 C24 C25 C26 C27 C28 C29 C30 C31 C32 C33 C34 C35 C36 C37: library part 电容-0402, "Capacitor"
C6: library part CAP, "Capacitor, chip, ceramic"
D2: library part Diode_SMA, "Diode"
D4 D5: "40V"
J1: Package=None
L1 L2: library part 电感-201612
LED1: library part LED, "LED GRN SGL RA 25mA 4.1V SMD"
P1 P2: "Header, 6-Pin, Right Angle"
P3: "Header, 3-Pin"
Q2: "N-MOS"
Q3: "P-MOS"
R1 R2 R3 R4 R5 R6 R7 R8 R9 R10 R11 R12 R13 R14 R15 R16 R17 R18 R19 R20 R21 R22 R23 R24 R25 R26 R27 R28 R29 R30 R31 R33 R34 R35: library part 电阻-0402, "Resistor"
U1: "USB转TTL"
U2: library part ESP32-PICO
U3: library part SY8089, "LDO"
U4: library part DET402
U7: library part NRF24L01模块
U8: "DC-DC"
U10: "六轴传感器"
U11: Manufacturer="Texas Instruments", Manufacturer Part Number=SN65HVD232DR, Operating Temperature="-40°C ~ 85°C", Package / Case="8-SOIC (0.154\", 3.90mm Width)", Supplier Device Package=8-SOIC, Supplier Part Number 1=296-26344-2-ND, Voltage - Supply="3 V ~ 3.6 V"
U12: "ARM Cortex-M4 32-bit MCU+FPU, 210 DMIPS, 1024 kB Flash, 192 kB Internal RAM, 51 I/Os, 64-pin LQFP, -40 to 85 degC, Tray", I/Os (High Current)=51, Manufacturer=STMicroelectronics, Operating Frequency(F) (Processor speed) (MHz)=168, Supplier Part Number 1=497-11767-ND, Supply Voltage(Vcc) max (V)=3.6, Supply Voltage(Vcc) min (V)=1.8
VT1: library part SMT_TRIODE_NPN, "Surface mount NPN transistor, package SOT-23"
Y1: "Crystal"

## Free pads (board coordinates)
  rrect50% 2.54x2.032 smd far side: ""(-1.27,-21.946) ""(-1.194,-19.05)
  round 4 hole 3: ""(0,-25.908) ""(0,0) ""(38.862,-51.054) ""(41.656,0)
  rrect50% 2.032x3.81 smd far side: ""(4.318,-26.416) ""(8.128,-26.416)
  round 2 hole 2: ""(13.64,-1.626) ""(23.139,-4.115) ""(37.77,-3.073)

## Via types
v1: diameter 0.457, hole 0.254, Top1 to Bottom2, tented both sides, 178 vias
v2: diameter 1, hole 0.5, Top1 to Bottom2, tented both sides, 12 vias
v3: diameter 0.457, hole 0.254, Top1 to Bottom2, 2 vias

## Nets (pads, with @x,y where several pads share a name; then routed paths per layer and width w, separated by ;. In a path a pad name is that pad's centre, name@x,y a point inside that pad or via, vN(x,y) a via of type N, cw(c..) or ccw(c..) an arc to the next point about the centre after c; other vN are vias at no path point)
3V3: 1.4 C4.2 C5.2 C10.2 C13.2 C18.2 C19.2 C20.1 C21.2 C22.2 C25.2 C28.2 C29.2 C30.2 C31.2 C37.2 L2.2 LED1.A R2.1 R5.1 R7.2 R17.2 R19.2 R20.2 R21.2 R23.2 R25.2 R27.2 R28.2 R31.1 R33.2 U2.3 U2.4 U2.19 U2.37 U4.1 U10.8 U10.13 U11.3 U12.1 U12.19 U12.32 U12.48 U12.64 | length 56.6
  Top1 w0.3: R27.2@-0.127,-19.66 v1(0.787,-19.66) v1@0.813,-19.685 ; C37.2@29.032,-27.661 29.136,-27.557 29.358,-27.557 29.497,-27.418 v1(29.539,-27.418) ; v1@29.539,-27.557 29.639,-27.456 29.639,-27.143 29.889,-26.893 U2.37@29.889,-26.731 ; v1(32.309,-18.803) 32.351,-18.803 32.391,-18.763 32.835,-18.763 C22.2@32.842,-18.771 32.738,-18.875 32.738,-19.179 32.414,-19.504 32.414,-19.981 U2.19@32.389,-20.005 ; U2.3@36.002,-25.118 U2.4@36.002,-24.618 36.355,-24.618 36.485,-24.488 36.777,-24.488 C19.2@36.881,-24.384 ; v1(36.877,-29.462) R2.1@36.877,-28.878 ; v1(39.319,-3.581) 39.319,-4.65 LED1.A@39.368,-4.699
  Top1 w0.33: v1(10.236,-9.423) 10.744,-9.423 R20.2@10.82,-9.5 R19.2@10.82,-10.338 ; v1(10.236,-8.052) R21.2@10.82,-8.052 ; v1(10.287,-5.512) 10.802,-5.512 R23.2@10.827,-5.537 ; U11.3@15.494,-15.46 15.494,-14.249 C18.2@15.621,-14.122 v1(15.621,-13.538) ; C19.2@36.957,-24.384 C21.2@37.795,-24.384 v1(38.303,-24.384) ; R5.1@37.084,-18.409 37.109,-18.383 v1(37.109,-17.882)
  Top1 w0.39: v1(5.258,-9.931) 6.368,-9.931 U4.1@6.401,-9.965 ; U4.1@6.045,-9.721 v1(6.045,-8.611) ; v1(6.157,-11.288) U4.1@6.157,-10.178 ; v1(12.387,-5.12) 12.405,-5.12 12.605,-5.32 14.397,-5.32 1.4@14.402,-5.325 ; v1(25.425,-12.522) 25.425,-12.008 26.943,-10.49 33.299,-10.49 34.617,-11.808 34.617,-11.852 34.722,-11.957 v1(34.722,-12.014)
  Bottom2 w0.3: v1(7.01,-11.278) 7.053,-11.278 7.307,-11.023 R28.2@7.483,-11.023 ; 13.629,-19.679 13.629,-19.528 13.878,-19.279 U12.64@13.878,-18.529
  Bottom2 w0.33: R25.2@9.474,-8.382 v1(9.474,-7.798) ; v1(10.312,-16.154) C28.2@10.312,-16.789 11.061,-16.789 11.106,-16.744 12.063,-16.744 U12.1@12.078,-16.729 ; C31.2@15.113,-5.893 14.878,-6.128 U12.19@14.878,-7.429 14.893,-7.444 14.893,-8.364 15.175,-8.647 17.966,-8.647 18.468,-9.149 18.468,-9.248 19.08,-9.86 v1(19.082,-9.86) ; v1(17.272,1.6) 17.272,1.016 C20.1@17.323,0.965 17.234,0.876 17.234,0.47 17.221,0.457 17.221,0.32 17.363,0.178 17.363,-0.201 U10.8@17.403,-0.241 ; U10.13@20.254,-1.091 21.564,-1.091 21.654,-1.003 21.984,-1.003 v1(22.149,-0.838) ; v1(20.752,-16.104) 21.378,-16.729 U12.48@23.178,-16.729 ; U12.32@21.378,-7.429 21.378,-6.841 21.393,-6.826 22.257,-6.826 C30.2@22.276,-6.807 v1(22.276,-7.341)
  Bottom2 w0.39: v1(12.878,-20.396) C29.2@13.462,-20.396 13.521,-20.337 13.521,-19.787 13.629,-19.679 ; v1(15.113,-19.787) 15.113,-19.805 15.257,-19.949 15.257,-20.337 R7.2@15.316,-20.396 ; R17.2@18.161,-20.396 v1(18.745,-20.396) ; v1@25.4,-12.395 25.4,-11.836 C13.2@25.425,-11.811 R33.2@25.425,-10.922 ; R31.1@25.857,-13.03 25.916,-12.971 25.916,-12.489 v1(26.01,-12.395)
  other v1: 33.985,-17.399 33.38,-17.302 34.722,-17.297 34.036,-16.739 34.722,-16.612
3V3A: C1.2 C2.2 R2.2 U2.1 U2.43 U2.46 | length 8.2
  Top1 w0.28: U2.43@32.889,-26.731 32.893,-26.726 32.893,-26.213 33.096,-26.01 34.468,-26.01 ; U2.46@34.389,-26.731 34.389,-26.088 34.468,-26.01 ; U2.1@36.002,-26.118 35.987,-26.103 35.601,-26.103 35.508,-26.01 34.468,-26.01
  Top1 w0.3: U2.1@36.002,-26.118 36.005,-26.122 36.005,-27.098 36.013,-27.106 36.013,-27.936 C2.2@36.017,-27.94 ; C1.2@36.017,-28.854 C2.2@36.017,-27.94 ; R2.2@36.906,-27.864 36.868,-27.902 36.055,-27.902 C2.2@36.017,-27.94
  other v1: 36.009,-27.102
ADC1_1: U12.10
ADC2_1: U12.11
ADC3_1: U12.24
ADC4_1: U12.25
AGND: C32.1 C33.1 R26.1 U12.12 | length 4
  Top1 w0.33: v1(9.906,-11.836) 9.94,-11.836 10.055,-11.951 10.35,-11.951 R26.1@10.439,-12.04
  Bottom2 w0.3: v1(9.906,-11.836) 9.906,-11.794 9.578,-11.466 9.578,-11.305 C32.1@9.474,-11.201 C33.1@10.363,-11.201 10.391,-11.229 U12.12@12.078,-11.229
AVCC: C32.2 C33.2 R25.1 U12.13 | length 3.6
  Bottom2 w0.3: R25.1@9.474,-9.398 C32.2@9.474,-10.185 C33.2@10.363,-10.185 10.795,-10.617 11.024,-10.617 11.136,-10.729 U12.13@12.078,-10.729
BOOT_1: Q1.3 U2.23 | length 12.6
  Top1 w0.18: v1(30.302,-21.031) 30.354,-20.979 30.354,-20.041 U2.23@30.389,-20.005 ; v1(34.646,-29.794) 34.662,-29.811 34.662,-30.629 Q1.3@34.679,-30.646
  Bottom2 w0.18: v1(30.302,-21.031) 30.302,-21.106 30.175,-21.233 30.175,-23.927 31.039,-24.79 31.039,-25.476 34.646,-29.083 v1(34.646,-29.794)
BUZZ_1: Q2.1 R10.2 U12.35 | length 31.2
  Top1 w0.18: R10.2@1.092,-4.115 1.092,-4.76 1.382,-5.049 Q2.1@1.382,-5.282 1.382,-10.627 4.529,-13.775 12.438,-13.775 13.589,-12.624 19.177,-12.624 v1(21.571,-10.229)
  Bottom2 w0.18: v1@21.539,-10.262 v1(21.571,-10.229) U12.35@23.178,-10.229
CAN1_D_1: U11.1 U12.62 | length 6.2
  Top1 w0.18: v1(14.783,-16.759) 15.573,-16.759 15.693,-16.879 17.411,-16.879 17.973,-16.317 17.973,-15.521 U11.1@18.034,-15.46
  Bottom2 w0.18: v1(14.783,-16.759) 14.783,-16.833 14.878,-16.928 U12.62@14.878,-18.529
CAN1_H_1: P1.6 R24.1 U11.7 | length 7.9
  Top1 w0.254: v1(16.485,-21.742) 16.485,-21.488 16.764,-21.209 U11.7@16.764,-20.76
  Bottom2 w0.254: P1.6@12.811,-25.527 12.811,-25.27 13.36,-24.72 13.36,-23.749 13.894,-23.216 R24.1@16.078,-23.216 16.688,-22.606 16.688,-22.327 16.523,-22.162 16.523,-21.781 v1(16.485,-21.742)
CAN1_L_1: P1.5 R24.2 U11.6 | length 9.5
  Top1 w0.254: U11.6@15.494,-20.76 15.494,-21.227 v1@15.824,-21.557
  Bottom2 w0.254: P1.5@14.311,-25.527 14.311,-25.048 13.818,-24.555 13.818,-24.028 14.046,-23.8 16.51,-23.8 R24.2@17.094,-23.216 17.094,-21.634 16.806,-21.345 16.695,-21.234 16.274,-21.234 15.977,-21.532 15.977,-21.586 15.875,-21.687 v1(15.875,-21.742) v1@15.868,-21.749
CAN1_R_1: U11.4 U12.61 | length 7.9
  Top1 w0.18: U11.4@14.224,-15.46 14.224,-14.605 14.021,-14.402 13.386,-14.402 13.081,-14.707 13.081,-16.464 13.847,-17.229 v1(15.378,-17.229)
  Bottom2 w0.18: U12.61@15.378,-18.529 v1(15.378,-17.229) 15.378,-17.211 v1@15.392,-17.196
CAN2_D_1: U12.34
CAN2_R_1: U12.33
CP_Rx_1: U1.25 U2.41 | length 11
  Top1 w0.18: v1(31.877,-28.092) 31.891,-27.703 31.891,-27.313 31.889,-27.251 U2.41@31.889,-26.731 ; v1(37.313,-32.664) U1.25@38.697,-32.664
  Bottom2 w0.18: v1(31.877,-28.092) 31.877,-28.499 34.292,-30.914 34.292,-32.11 34.847,-32.664 v1(37.313,-32.664)
CP_Tx_1: R3.1 U2.40 | length 7.8
  Top1 w0.18: U2.40@31.389,-26.731 31.42,-26.978 v1(31.42,-27.508)
  Bottom2 w0.18: v1(31.42,-27.508) 31.389,-27.539 31.389,-28.544 33.96,-31.115 33.96,-32.715 34.392,-33.147 v1(34.468,-33.147)
DTR_1: Q1.4 R4.1 U1.28 | length 6.7
  Top1 w0.18: R4.1@33.655,-31.877 33.87,-32.092 Q1.4@34.679,-32.092 34.679,-32.342 35.179,-32.842 35.179,-33.731 35.612,-34.164 U1.28@38.697,-34.164
ENCODER1_A_1: U12.50
ENCODER1_B_1: U12.55
ENCODER2_A_1: U12.37
ENCODER2_B_1: U12.38
ESP_EN_1: C3.1 Q1.6 R5.2 U2.9 | length 17.4
  Top1 w0.18: Q1.6@35.679,-32.092 35.684,-32.097 36.073,-32.097 v1(36.078,-32.102) ; U2.9@36.002,-22.118 v1(37.242,-22.118) 37.973,-21.387 C3.1@37.973,-19.425 R5.2@37.084,-19.425
  Bottom2 w0.18: v1(36.078,-32.102) 36.014,-32.102 35.265,-31.354 35.265,-22.901 36.048,-22.118 v1(37.242,-22.118)
FLASH_CLK_1: U2.31
FLASH_CS_1: U2.25
FLASH_SD0_1: U2.27
FLASH_SD1_1: U2.33
FLASH_SD2_1: U2.30
FLASH_SD3_1: U2.32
